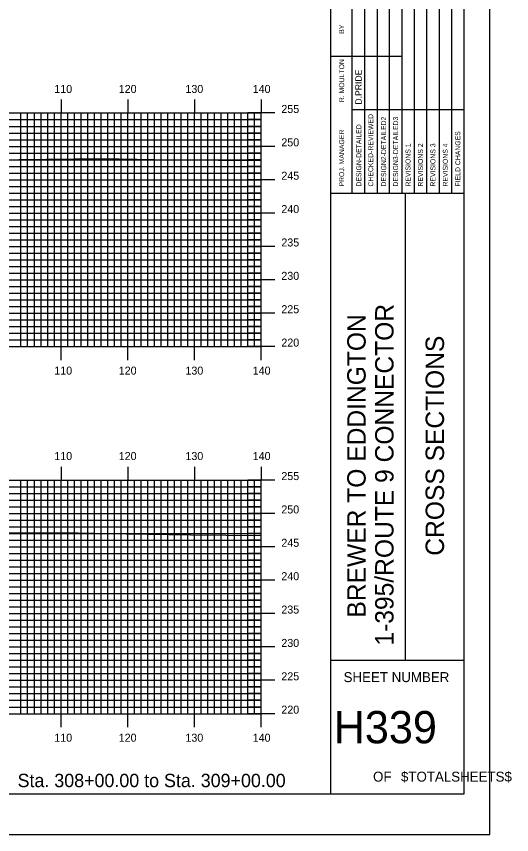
# Model space of a CAD drawing. Extents: x 1817670 to 1818013, y 442591 to 442811.
# Drawn here: x 1817938.9 to 1818013.1, y 442590.5 to 442713.1 of the extents above; entities that cross this region are included whole.
import ezdxf

# ---------------------------------------------------------------- set-up
doc = ezdxf.new("R2010")
doc.units = 0
for name, color, linetype in [('BORDER', 7, 'Continuous'), ('H_V ANNOTATION', 7, 'Continuous'), ('MAJOR', 7, 'Continuous'), ('MINOR', 7, 'Continuous'), ('PLOT BOUNDARY', 7, 'Continuous'), ('S_Roadway_Centerline', 7, 'Continuous')]:
    doc.layers.add(name, color=color, linetype=linetype)

msp = doc.modelspace()

# ---------------------------------------------------------------- linework, layer by layer
at = {"layer": 'BORDER'}
for p, q in [((1817986.01, 442596.67), (1817986.01, 442806.67)), ((1817986.01, 442686.67), (1818006.01, 442686.67)), ((1817997.19, 442616.67), (1817997.19, 442686.67)), ((1817986.01, 442616.67), (1818006.01, 442616.67))]:
    msp.add_line(p, q, dxfattribs=at)
msp.add_lwpolyline([(1817686.01, 442596.67), (1818006.01, 442596.67), (1818006.01, 442806.67), (1817686.01, 442806.67)], close=True, dxfattribs=at)
for points in [[(1817991.11, 442686.68), (1817991.11, 442721.67)], [(1817992.97, 442721.67), (1817992.97, 442686.68)], [(1817994.83, 442686.68), (1817994.83, 442721.67)], [(1817996.7, 442686.68), (1817996.7, 442721.67)], [(1817998.56, 442686.68), (1817998.56, 442721.67)], [(1818000.42, 442686.68), (1818000.42, 442721.67)], [(1818002.29, 442686.68), (1818002.29, 442721.67)], [(1818004.15, 442686.68), (1818004.15, 442721.67)], [(1817989.24, 442686.68), (1817989.24, 442720.26)], [(1817986.01, 442707.17), (1817989.24, 442707.17)], [(1817989.24, 442707.17), (1817996.7, 442707.17)], [(1817989.24, 442699.17), (1818006.01, 442699.17)]]:
    msp.add_lwpolyline(points, dxfattribs=at)
at = {"layer": 'MAJOR'}
for p, q in [((1817945.61, 442700.67), (1817945.61, 442698.67)), ((1817955.61, 442700.67), (1817955.61, 442698.67)), ((1817965.61, 442700.67), (1817965.61, 442698.67)), ((1817975.61, 442700.67), (1817975.61, 442698.67)), ((1817695.61, 442698.67), (1817975.61, 442698.67)), ((1817695.61, 442698.67), (1817975.61, 442698.67)), ((1817945.61, 442663.67), (1817945.61, 442698.67)), ((1817955.61, 442663.67), (1817955.61, 442698.67)), ((1817965.61, 442663.67), (1817965.61, 442698.67)), ((1817977.62, 442698.67), (1817973.61, 442698.67)), ((1817975.61, 442663.67), (1817975.61, 442698.67)), ((1817975.61, 442663.67), (1817975.61, 442698.67)), ((1817695.61, 442693.67), (1817975.61, 442693.67)), ((1817977.62, 442693.67), (1817973.61, 442693.67)), ((1817695.61, 442688.67), (1817975.61, 442688.67)), ((1817977.62, 442688.67), (1817973.61, 442688.67)), ((1817695.61, 442683.67), (1817975.61, 442683.67)), ((1817977.62, 442683.67), (1817973.61, 442683.67)), ((1817695.61, 442678.67), (1817975.61, 442678.67)), ((1817977.62, 442678.67), (1817973.61, 442678.67)), ((1817695.61, 442673.67), (1817975.61, 442673.67)), ((1817977.62, 442673.67), (1817973.61, 442673.67)), ((1817695.61, 442668.67), (1817975.61, 442668.67)), ((1817977.62, 442668.67), (1817973.61, 442668.67)), ((1817695.61, 442663.67), (1817975.61, 442663.67)), ((1817695.61, 442663.67), (1817975.61, 442663.67)), ((1817945.61, 442661.66), (1817945.61, 442663.67)), ((1817955.61, 442661.66), (1817955.61, 442663.67)), ((1817965.61, 442661.66), (1817965.61, 442663.67)), ((1817977.62, 442663.67), (1817973.61, 442663.67)), ((1817975.61, 442661.66), (1817975.61, 442663.67)), ((1817945.61, 442645.67), (1817945.61, 442643.67)), ((1817955.61, 442645.67), (1817955.61, 442643.67)), ((1817965.61, 442645.67), (1817965.61, 442643.67)), ((1817975.61, 442645.67), (1817975.61, 442643.67)), ((1817695.61, 442643.67), (1817975.61, 442643.67)), ((1817695.61, 442643.67), (1817975.61, 442643.67)), ((1817945.61, 442608.67), (1817945.61, 442643.67)), ((1817955.61, 442608.67), (1817955.61, 442643.67)), ((1817965.61, 442608.67), (1817965.61, 442643.67)), ((1817977.62, 442643.67), (1817973.61, 442643.67)), ((1817975.61, 442608.67), (1817975.61, 442643.67)), ((1817975.61, 442608.67), (1817975.61, 442643.67)), ((1817695.61, 442638.67), (1817975.61, 442638.67)), ((1817977.62, 442638.67), (1817973.61, 442638.67)), ((1817695.61, 442633.67), (1817975.61, 442633.67)), ((1817977.62, 442633.67), (1817973.61, 442633.67)), ((1817695.61, 442628.67), (1817975.61, 442628.67)), ((1817977.62, 442628.67), (1817973.61, 442628.67)), ((1817695.61, 442623.67), (1817975.61, 442623.67)), ((1817977.62, 442623.67), (1817973.61, 442623.67)), ((1817695.61, 442618.67), (1817975.61, 442618.67)), ((1817977.62, 442618.67), (1817973.61, 442618.67)), ((1817695.61, 442613.67), (1817975.61, 442613.67)), ((1817977.62, 442613.67), (1817973.61, 442613.67)), ((1817695.61, 442608.67), (1817975.61, 442608.67)), ((1817695.61, 442608.67), (1817975.61, 442608.67)), ((1817945.61, 442606.66), (1817945.61, 442608.67)), ((1817955.61, 442606.66), (1817955.61, 442608.67)), ((1817965.61, 442606.66), (1817965.61, 442608.67)), ((1817977.62, 442608.67), (1817973.61, 442608.67)), ((1817975.61, 442606.66), (1817975.61, 442608.67))]:
    msp.add_line(p, q, dxfattribs=at)
at = {"layer": 'MINOR'}
for p, q in [((1817939.61, 442663.67), (1817939.61, 442698.67)), ((1817940.61, 442663.67), (1817940.61, 442698.67)), ((1817941.61, 442663.67), (1817941.61, 442698.67)), ((1817942.61, 442663.67), (1817942.61, 442698.67)), ((1817943.61, 442663.67), (1817943.61, 442698.67)), ((1817944.61, 442663.67), (1817944.61, 442698.67)), ((1817946.61, 442663.67), (1817946.61, 442698.67)), ((1817947.61, 442663.67), (1817947.61, 442698.67)), ((1817948.61, 442663.67), (1817948.61, 442698.67)), ((1817949.61, 442663.67), (1817949.61, 442698.67)), ((1817950.61, 442663.67), (1817950.61, 442698.67)), ((1817951.61, 442663.67), (1817951.61, 442698.67)), ((1817952.61, 442663.67), (1817952.61, 442698.67)), ((1817953.61, 442663.67), (1817953.61, 442698.67)), ((1817954.61, 442663.67), (1817954.61, 442698.67)), ((1817956.61, 442663.67), (1817956.61, 442698.67)), ((1817957.61, 442663.67), (1817957.61, 442698.67)), ((1817958.61, 442663.67), (1817958.61, 442698.67)), ((1817959.61, 442663.67), (1817959.61, 442698.67)), ((1817960.61, 442663.67), (1817960.61, 442698.67)), ((1817961.61, 442663.67), (1817961.61, 442698.67)), ((1817962.61, 442663.67), (1817962.61, 442698.67)), ((1817963.61, 442663.67), (1817963.61, 442698.67)), ((1817964.61, 442663.67), (1817964.61, 442698.67)), ((1817966.61, 442663.67), (1817966.61, 442698.67)), ((1817967.61, 442663.67), (1817967.61, 442698.67)), ((1817968.61, 442663.67), (1817968.61, 442698.67)), ((1817969.61, 442663.67), (1817969.61, 442698.67)), ((1817970.61, 442663.67), (1817970.61, 442698.67)), ((1817971.61, 442663.67), (1817971.61, 442698.67)), ((1817972.61, 442663.67), (1817972.61, 442698.67)), ((1817973.61, 442663.67), (1817973.61, 442698.67)), ((1817974.61, 442663.67), (1817974.61, 442698.67)), ((1817695.61, 442697.67), (1817975.61, 442697.67)), ((1817695.61, 442696.67), (1817975.61, 442696.67)), ((1817975.61, 442697.67), (1817973.61, 442697.67)), ((1817975.61, 442696.67), (1817973.61, 442696.67)), ((1817695.61, 442695.67), (1817975.61, 442695.67)), ((1817975.61, 442695.67), (1817973.61, 442695.67)), ((1817695.61, 442694.67), (1817975.61, 442694.67)), ((1817975.61, 442694.67), (1817973.61, 442694.67)), ((1817695.61, 442692.67), (1817975.61, 442692.67)), ((1817975.61, 442692.67), (1817973.61, 442692.67)), ((1817695.61, 442691.67), (1817975.61, 442691.67)), ((1817695.61, 442690.67), (1817975.61, 442690.67)), ((1817975.61, 442691.67), (1817973.61, 442691.67)), ((1817975.61, 442690.67), (1817973.61, 442690.67)), ((1817695.61, 442689.67), (1817975.61, 442689.67)), ((1817975.61, 442689.67), (1817973.61, 442689.67)), ((1817695.61, 442687.67), (1817975.61, 442687.67)), ((1817975.61, 442687.67), (1817973.61, 442687.67)), ((1817695.61, 442686.67), (1817975.61, 442686.67)), ((1817695.61, 442685.67), (1817975.61, 442685.67)), ((1817975.61, 442686.67), (1817973.61, 442686.67)), ((1817975.61, 442685.67), (1817973.61, 442685.67)), ((1817695.61, 442684.67), (1817975.61, 442684.67)), ((1817975.61, 442684.67), (1817973.61, 442684.67)), ((1817695.61, 442682.67), (1817975.61, 442682.67)), ((1817975.61, 442682.67), (1817973.61, 442682.67)), ((1817695.61, 442681.67), (1817975.61, 442681.67)), ((1817975.61, 442681.67), (1817973.61, 442681.67)), ((1817695.61, 442680.67), (1817975.61, 442680.67)), ((1817695.61, 442679.67), (1817975.61, 442679.67)), ((1817975.61, 442680.67), (1817973.61, 442680.67)), ((1817975.61, 442679.67), (1817973.61, 442679.67)), ((1817695.61, 442677.67), (1817975.61, 442677.67)), ((1817975.61, 442677.67), (1817973.61, 442677.67)), ((1817695.61, 442676.67), (1817975.61, 442676.67)), ((1817975.61, 442676.67), (1817973.61, 442676.67)), ((1817695.61, 442675.67), (1817975.61, 442675.67)), ((1817695.61, 442674.67), (1817975.61, 442674.67)), ((1817975.61, 442675.67), (1817973.61, 442675.67)), ((1817975.61, 442674.67), (1817973.61, 442674.67)), ((1817695.61, 442672.67), (1817975.61, 442672.67)), ((1817975.61, 442672.67), (1817973.61, 442672.67)), ((1817695.61, 442671.67), (1817975.61, 442671.67)), ((1817975.61, 442671.67), (1817973.61, 442671.67)), ((1817695.61, 442670.67), (1817975.61, 442670.67)), ((1817695.61, 442669.67), (1817975.61, 442669.67)), ((1817975.61, 442670.67), (1817973.61, 442670.67)), ((1817975.61, 442669.67), (1817973.61, 442669.67)), ((1817695.61, 442667.67), (1817975.61, 442667.67)), ((1817975.61, 442667.67), (1817973.61, 442667.67)), ((1817695.61, 442666.67), (1817975.61, 442666.67)), ((1817975.61, 442666.67), (1817973.61, 442666.67)), ((1817695.61, 442665.67), (1817975.61, 442665.67)), ((1817975.61, 442665.67), (1817973.61, 442665.67)), ((1817695.61, 442664.67), (1817975.61, 442664.67)), ((1817975.61, 442664.67), (1817973.61, 442664.67)), ((1817939.61, 442608.67), (1817939.61, 442643.67)), ((1817940.61, 442608.67), (1817940.61, 442643.67)), ((1817941.61, 442608.67), (1817941.61, 442643.67)), ((1817942.61, 442608.67), (1817942.61, 442643.67)), ((1817943.61, 442608.67), (1817943.61, 442643.67)), ((1817944.61, 442608.67), (1817944.61, 442643.67)), ((1817946.61, 442608.67), (1817946.61, 442643.67)), ((1817947.61, 442608.67), (1817947.61, 442643.67)), ((1817948.61, 442608.67), (1817948.61, 442643.67)), ((1817949.61, 442608.67), (1817949.61, 442643.67)), ((1817950.61, 442608.67), (1817950.61, 442643.67)), ((1817951.61, 442608.67), (1817951.61, 442643.67)), ((1817952.61, 442608.67), (1817952.61, 442643.67)), ((1817953.61, 442608.67), (1817953.61, 442643.67)), ((1817954.61, 442608.67), (1817954.61, 442643.67)), ((1817956.61, 442608.67), (1817956.61, 442643.67)), ((1817957.61, 442608.67), (1817957.61, 442643.67)), ((1817958.61, 442608.67), (1817958.61, 442643.67)), ((1817959.61, 442608.67), (1817959.61, 442643.67)), ((1817960.61, 442608.67), (1817960.61, 442643.67)), ((1817961.61, 442608.67), (1817961.61, 442643.67)), ((1817962.61, 442608.67), (1817962.61, 442643.67)), ((1817963.61, 442608.67), (1817963.61, 442643.67)), ((1817964.61, 442608.67), (1817964.61, 442643.67)), ((1817966.61, 442608.67), (1817966.61, 442643.67)), ((1817967.61, 442608.67), (1817967.61, 442643.67)), ((1817968.61, 442608.67), (1817968.61, 442643.67)), ((1817969.61, 442608.67), (1817969.61, 442643.67)), ((1817970.61, 442608.67), (1817970.61, 442643.67)), ((1817971.61, 442608.67), (1817971.61, 442643.67)), ((1817972.61, 442608.67), (1817972.61, 442643.67)), ((1817973.61, 442608.67), (1817973.61, 442643.67)), ((1817974.61, 442608.67), (1817974.61, 442643.67)), ((1817695.61, 442642.67), (1817975.61, 442642.67)), ((1817695.61, 442641.67), (1817975.61, 442641.67)), ((1817975.61, 442642.67), (1817973.61, 442642.67)), ((1817975.61, 442641.67), (1817973.61, 442641.67)), ((1817695.61, 442640.67), (1817975.61, 442640.67)), ((1817975.61, 442640.67), (1817973.61, 442640.67)), ((1817695.61, 442639.67), (1817975.61, 442639.67)), ((1817975.61, 442639.67), (1817973.61, 442639.67)), ((1817695.61, 442637.67), (1817975.61, 442637.67)), ((1817695.61, 442636.67), (1817975.61, 442636.67)), ((1817975.61, 442637.67), (1817973.61, 442637.67)), ((1817975.61, 442636.67), (1817973.61, 442636.67)), ((1817695.61, 442635.67), (1817975.61, 442635.67)), ((1817975.61, 442635.67), (1817973.61, 442635.67)), ((1817695.61, 442634.67), (1817975.61, 442634.67)), ((1817975.61, 442634.67), (1817973.61, 442634.67)), ((1817695.61, 442632.67), (1817975.61, 442632.67)), ((1817695.61, 442631.67), (1817975.61, 442631.67)), ((1817975.61, 442632.67), (1817973.61, 442632.67)), ((1817975.61, 442631.67), (1817973.61, 442631.67)), ((1817695.61, 442630.67), (1817975.61, 442630.67)), ((1817975.61, 442630.67), (1817973.61, 442630.67)), ((1817695.61, 442629.67), (1817975.61, 442629.67)), ((1817975.61, 442629.67), (1817973.61, 442629.67)), ((1817695.61, 442627.67), (1817975.61, 442627.67)), ((1817975.61, 442627.67), (1817973.61, 442627.67)), ((1817695.61, 442626.67), (1817975.61, 442626.67)), ((1817695.61, 442625.67), (1817975.61, 442625.67)), ((1817975.61, 442626.67), (1817973.61, 442626.67)), ((1817975.61, 442625.67), (1817973.61, 442625.67)), ((1817695.61, 442624.67), (1817975.61, 442624.67)), ((1817975.61, 442624.67), (1817973.61, 442624.67)), ((1817695.61, 442622.67), (1817975.61, 442622.67)), ((1817975.61, 442622.67), (1817973.61, 442622.67)), ((1817695.61, 442621.67), (1817975.61, 442621.67)), ((1817695.61, 442620.67), (1817975.61, 442620.67)), ((1817975.61, 442621.67), (1817973.61, 442621.67)), ((1817975.61, 442620.67), (1817973.61, 442620.67)), ((1817695.61, 442619.67), (1817975.61, 442619.67)), ((1817975.61, 442619.67), (1817973.61, 442619.67)), ((1817695.61, 442617.67), (1817975.61, 442617.67)), ((1817975.61, 442617.67), (1817973.61, 442617.67)), ((1817695.61, 442616.67), (1817975.61, 442616.67)), ((1817975.61, 442616.67), (1817973.61, 442616.67)), ((1817695.61, 442615.67), (1817975.61, 442615.67)), ((1817695.61, 442614.67), (1817975.61, 442614.67)), ((1817975.61, 442615.67), (1817973.61, 442615.67)), ((1817975.61, 442614.67), (1817973.61, 442614.67)), ((1817695.61, 442612.67), (1817975.61, 442612.67)), ((1817975.61, 442612.67), (1817973.61, 442612.67)), ((1817695.61, 442611.67), (1817975.61, 442611.67)), ((1817975.61, 442611.67), (1817973.61, 442611.67)), ((1817695.61, 442610.67), (1817975.61, 442610.67)), ((1817695.61, 442609.67), (1817975.61, 442609.67)), ((1817975.61, 442610.67), (1817973.61, 442610.67)), ((1817975.61, 442609.67), (1817973.61, 442609.67))]:
    msp.add_line(p, q, dxfattribs=at)
at = {"layer": 'PLOT BOUNDARY'}
msp.add_lwpolyline([(1817669.83, 442590.55), (1818009.83, 442590.55), (1818009.83, 442810.55), (1817669.83, 442810.55)], close=True, dxfattribs=at)
at = {"layer": 'S_Roadway_Centerline'}
for points in [[(1817864.27, 442689.84), (1817866.79, 442689.88), (1817871.18, 442689.99), (1817884.14, 442690.33), (1817894.17, 442690.79), (1817901.31, 442691.06), (1817905.48, 442691.19), (1817918.69, 442691.51), (1817924.2, 442691.56), (1817935.09, 442691.55), (1817939.27, 442691.69), (1817951.66, 442691.85), (1817959.63, 442691.72), (1817969.2, 442691.61), (1817975.61, 442691.58)], [(1817863.69, 442634.99), (1817889.78, 442635.42), (1817897.45, 442635.6), (1817911.25, 442635.5), (1817914.57, 442635.55), (1817916.52, 442635.54), (1817925.03, 442635.66), (1817930.06, 442635.72), (1817931.11, 442635.74), (1817932.88, 442635.75), (1817948.16, 442635.77), (1817955.38, 442635.61), (1817965.03, 442635.48), (1817975.61, 442635.37)]]:
    msp.add_lwpolyline(points, dxfattribs=at)

# ---------------------------------------------------------------- texts
at = {"layer": 'BORDER'}
for s, height, p in [('BY', 0.743, (1817988.02, 442710.54)), ('R. MOULTON', 0.745, (1817988.02, 442700.28)), ('D.PRIDE', 0.969, (1817990.66, 442699.92)), ('CHECKED-REVIEWED', 0.7455, (1817992.37, 442687.65)), ('DESIGN-DETAILED', 0.7455, (1817990.59, 442687.65)), ('DESIGN2-DETAILED2', 0.7455, (1817994.31, 442687.65)), ('DESIGN3-DETAILED3', 0.7455, (1817996.1, 442687.65)), ('PROJ. MANAGER', 0.7455, (1817988.02, 442687.65)), ('FIELD CHANGES', 0.7455, (1818005.42, 442687.65)), ('REVISIONS 1', 0.7455, (1817997.96, 442687.65)), ('REVISIONS 2', 0.7455, (1817999.83, 442687.65)), ('REVISIONS 3', 0.7455, (1818001.69, 442687.65)), ('REVISIONS 4', 0.7455, (1818003.55, 442687.65)), ('1-395/ROUTE 9 CONNECTOR', 2.7557, (1817995.42, 442618.87)), ('BREWER TO EDDINGTON', 2.7557, (1817991.24, 442623.07)), ('CROSS SECTIONS', 2.7557, (1818002.98, 442632.34))]:
    msp.add_text(s, height=height, rotation=90, dxfattribs=at).set_placement(p)
for s, height, p in [('SHEET NUMBER', 1.4905, (1817987.94, 442613.4)), ('H339', 4.839, (1817986.45, 442604.23)), ('OF', 1.491, (1817992.35, 442598.49)), ('$TOTALSHEETS$', 1.4905, (1817996.53, 442598.49))]:
    msp.add_text(s, height=height, dxfattribs=at).set_placement(p)
at = {"layer": 'H_V ANNOTATION'}
for s, height, p in [('110', 1.2, (1817944.6, 442701.67)), ('120', 1.2, (1817954.25, 442701.67)), ('130', 1.2, (1817964.24, 442701.67)), ('140', 1.2, (1817974.32, 442701.67)), ('255', 1.2, (1817978.61, 442698.67)), ('250', 1.2, (1817978.61, 442693.67)), ('245', 1.2, (1817978.61, 442688.67)), ('240', 1.2, (1817978.61, 442683.67)), ('235', 1.2, (1817978.61, 442678.67)), ('230', 1.2, (1817978.61, 442673.67)), ('225', 1.2, (1817978.61, 442668.67)), ('220', 1.2, (1817978.61, 442663.67)), ('110', 1.2, (1817944.6, 442659.47)), ('120', 1.2, (1817954.25, 442659.47)), ('130', 1.2, (1817964.24, 442659.47)), ('140', 1.2, (1817974.32, 442659.47)), ('110', 1.2, (1817944.6, 442646.67)), ('120', 1.2, (1817954.25, 442646.67)), ('130', 1.2, (1817964.24, 442646.67)), ('140', 1.2, (1817974.32, 442646.67)), ('255', 1.2, (1817978.61, 442643.67)), ('250', 1.2, (1817978.61, 442638.67)), ('245', 1.2, (1817978.61, 442633.67)), ('240', 1.2, (1817978.61, 442628.67)), ('235', 1.2, (1817978.61, 442623.67)), ('230', 1.2, (1817978.61, 442618.67)), ('225', 1.2, (1817978.61, 442613.67)), ('220', 1.2, (1817978.61, 442608.67)), ('110', 1.2, (1817944.6, 442604.47)), ('120', 1.2, (1817954.25, 442604.47)), ('130', 1.2, (1817964.24, 442604.47)), ('140', 1.2, (1817974.32, 442604.47)), ('Sta. 308+00.00 to Sta. 309+00.00', 2.0004, (1817939.1, 442597.66))]:
    msp.add_text(s, height=height, dxfattribs=at).set_placement(p)

doc.saveas('drawing.dxf')
